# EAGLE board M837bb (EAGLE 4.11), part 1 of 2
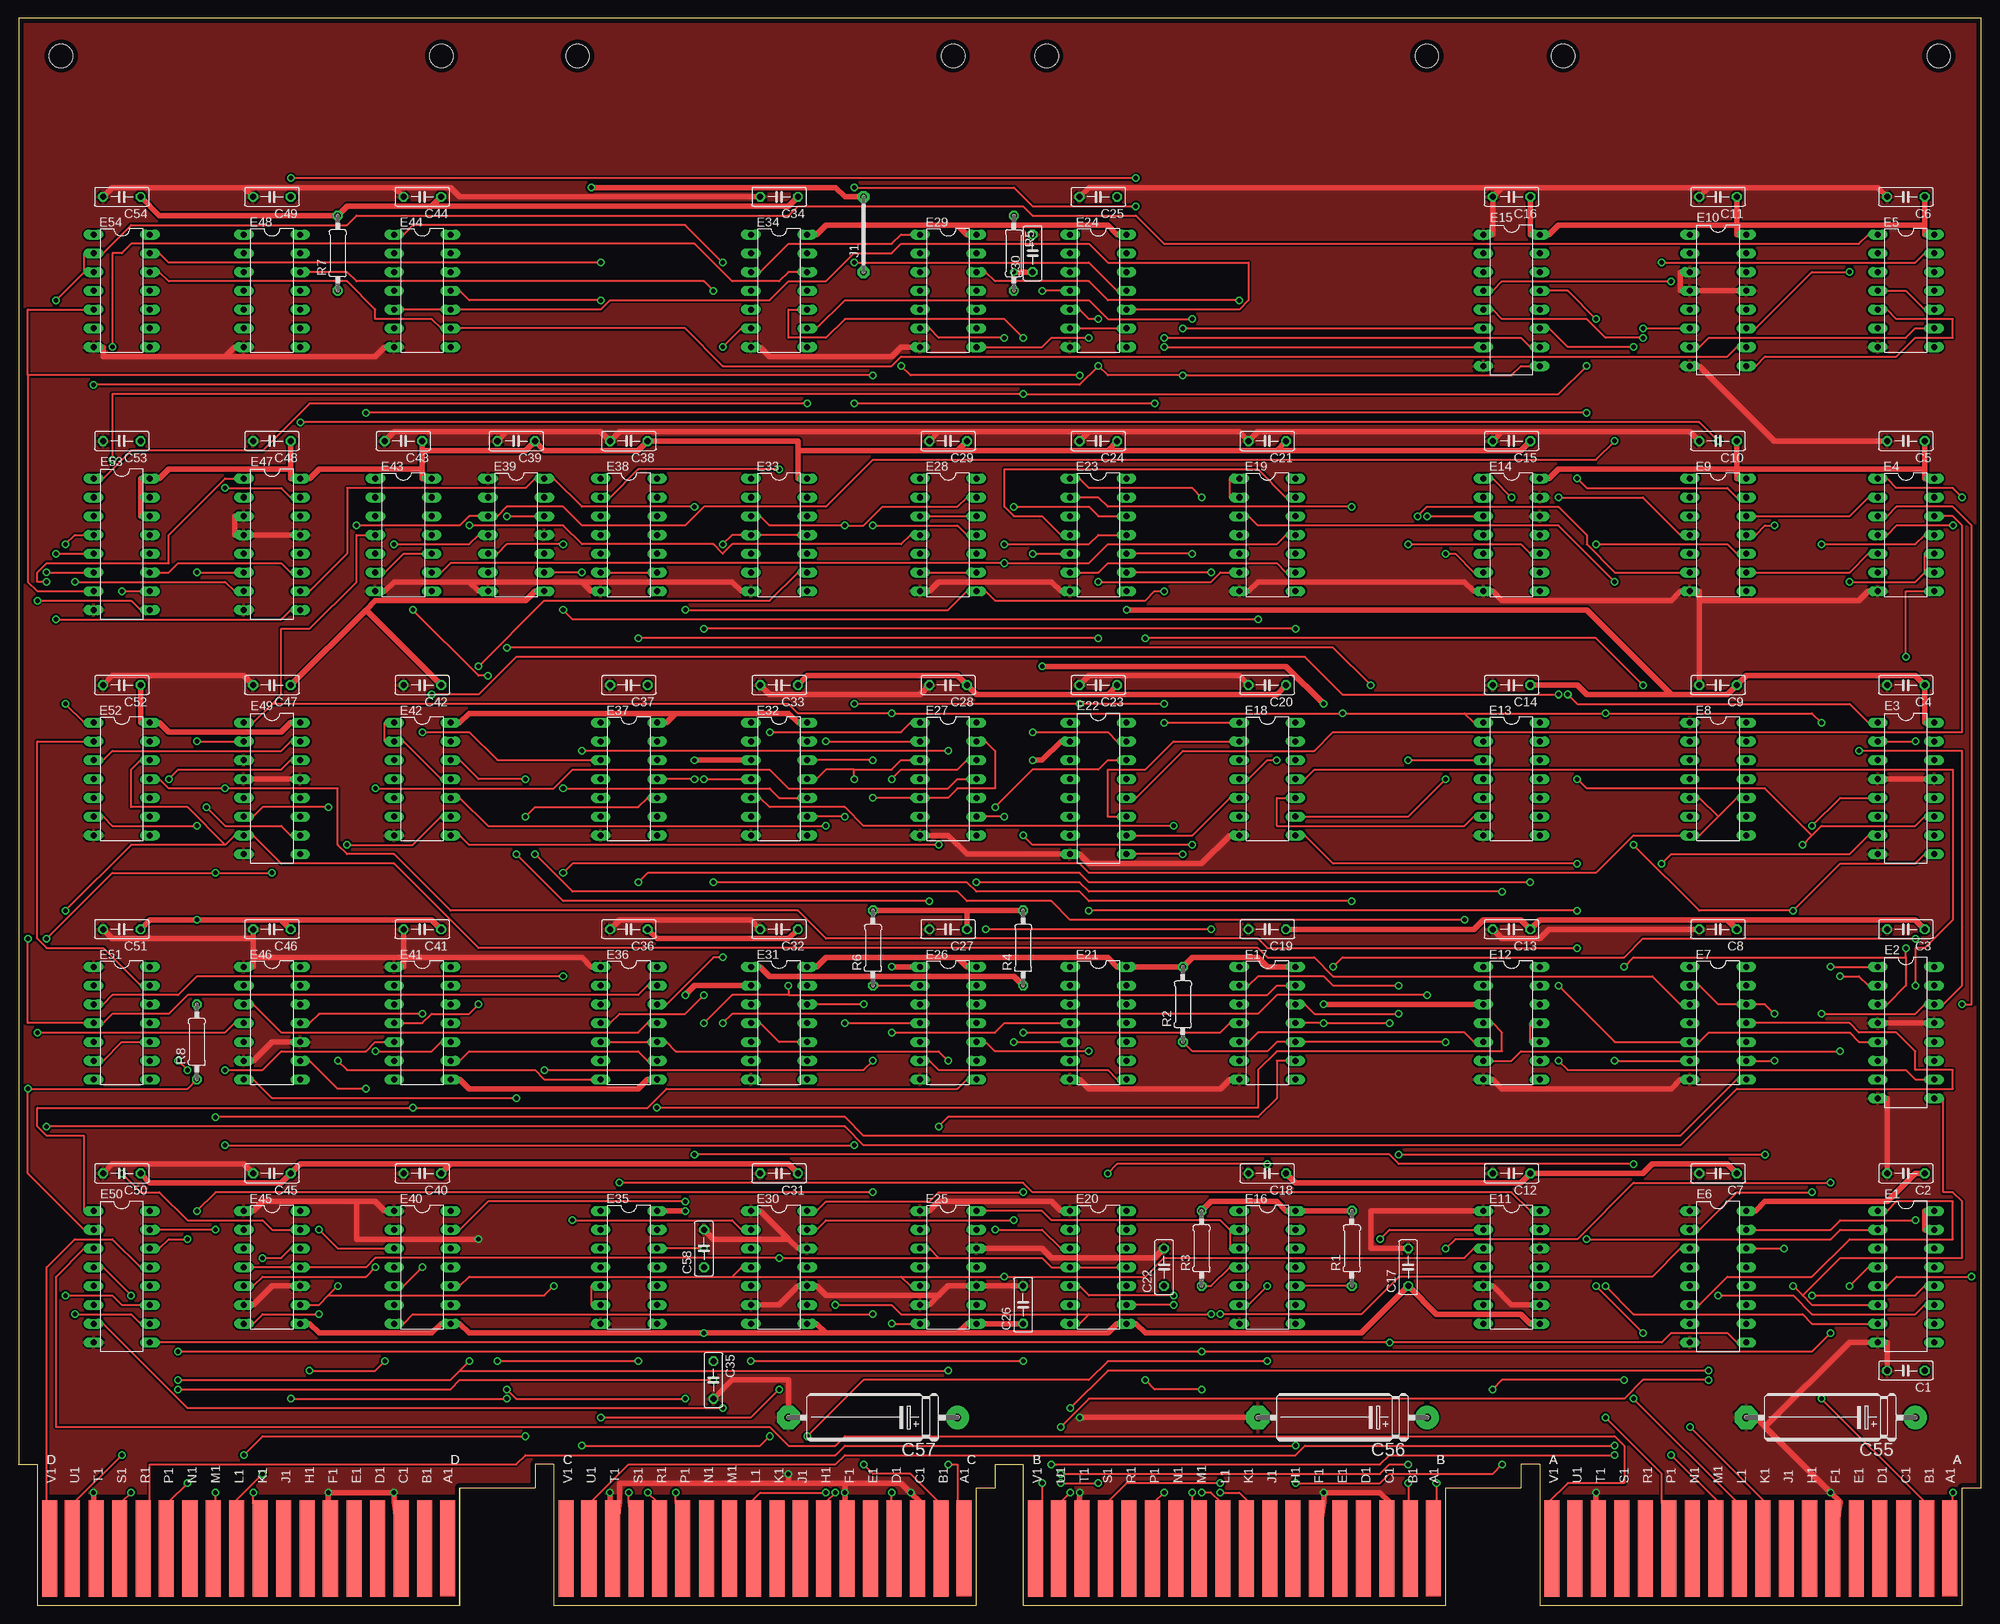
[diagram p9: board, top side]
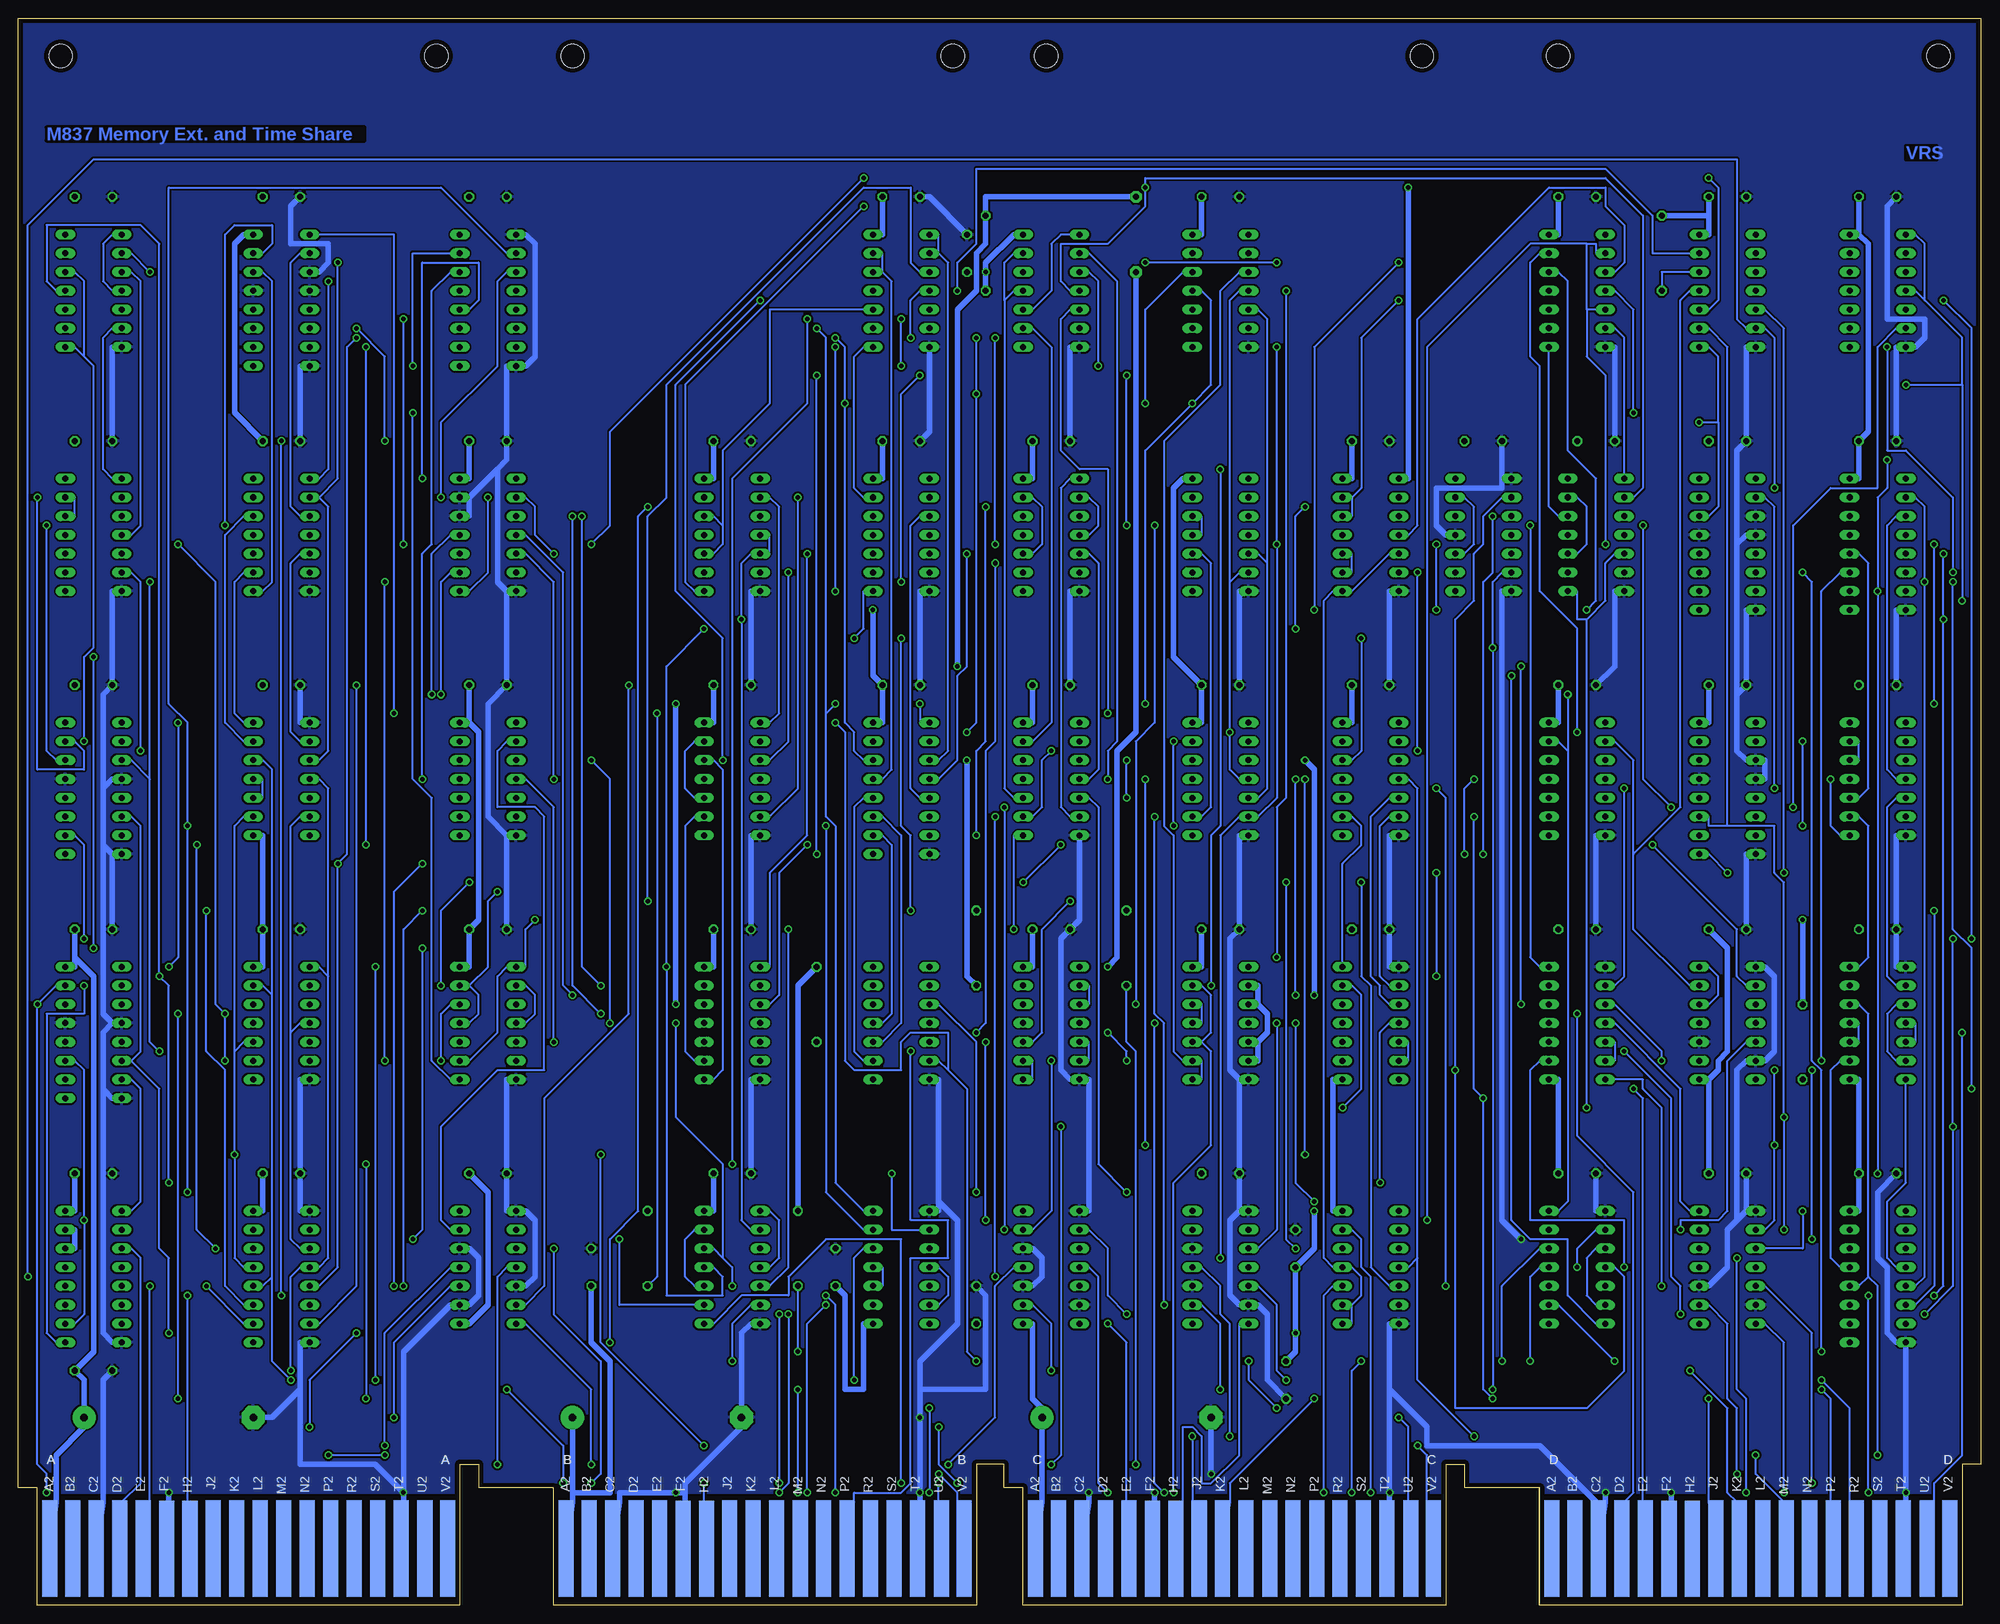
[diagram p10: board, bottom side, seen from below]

Size 265.43 x 214.63 mm. Coordinates in mm from the lower left corner, seen from the top.
Copper layers (1*16): Top 0.035mm / dielectric 1.5mm / Bottom 0.035mm
Design rules "default": minimum track width 10mil, minimum drill 24mil, track to track 8mil, track to pad 8mil, pad to pad 8mil, via to via 8mil, smd to smd 8mil, copper to edge 25mil, drill to drill 8mil, minimum pad ring 10mil, minimum via ring 8mil, stop-mask expansion 4mil, vias tented up to drill 0mil, thermal gap 10mil
Net classes: 1 Supply: width 0.762 mm

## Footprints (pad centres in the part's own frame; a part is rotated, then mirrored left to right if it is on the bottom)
C050-025X075 = drill 0.813 octagon: 1 -2.54,0; 2 2.54,0
E22-6 = drill 1.016 pad 3.15 round: + -11.43,0 | drill 1.016 pad 3.15 octagon: - 11.43,0
DIL16 = drill 0.813 long: 1 -8.89,-3.81; 2 -6.35,-3.81; 3 -3.81,-3.81; 4 -1.27,-3.81; 5 1.27,-3.81; 6 3.81,-3.81; 7 6.35,-3.81; 8 8.89,-3.81; 9 8.89,3.81; 10 6.35,3.81; 11 3.81,3.81; 12 1.27,3.81; 13 -1.27,3.81; 14 -3.81,3.81; 15 -6.35,3.81; 16 -8.89,3.81
DIL14 = drill 0.813 long: 1 -7.62,-3.81; 2 -5.08,-3.81; 3 -2.54,-3.81; 4 0,-3.81; 5 2.54,-3.81; 6 5.08,-3.81; 7 7.62,-3.81; 8 7.62,3.81; 9 5.08,3.81; 10 2.54,3.81; 11 0,3.81; 12 -2.54,3.81; 13 -5.08,3.81; 14 -7.62,3.81
EDGE-CON8 = smd 2.032 x 13.017: AA1 261.223,7.709; AB1 258.118,7.684; AC1 254.956,7.684; AD1 251.765,7.684; AE1 248.59,7.693; AF1 245.389,7.668; AH1 242.24,7.668; AJ1 239.09,7.668; AK1 235.915,7.668; AL1 232.74,7.693; AM1 229.54,7.693; AN1 226.39,7.693; AP1 223.19,7.668; AR1 220.04,7.668; AS1 216.865,7.693; AT1 213.69,7.693; AU1 210.49,7.693; AV1 207.404,7.668; BA1 191.373,7.709; BB1 188.268,7.684; BC1 185.106,7.684; BD1 181.915,7.684; BE1 178.74,7.693; BF1 175.539,7.668; BH1 172.39,7.668; BJ1 169.24,7.668; BK1 166.065,7.668; BL1 162.89,7.693; BM1 159.69,7.693; BN1 156.54,7.693; BP1 153.34,7.668; BR1 150.19,7.668; BS1 147.015,7.693; BT1 143.84,7.693; BU1 140.64,7.693; BV1 137.554,7.668; CA1 127.873,7.709; CB1 124.768,7.684; CC1 121.606,7.684; CD1 118.415,7.684; CE1 115.24,7.693; CF1 112.039,7.668; CH1 108.89,7.668; CJ1 105.74,7.668; CK1 102.565,7.668; CL1 99.39,7.693; CM1 96.19,7.693; CN1 93.04,7.693; CP1 89.84,7.668; CR1 86.69,7.668; CS1 83.515,7.693; CT1 80.34,7.693; CU1 77.14,7.693; CV1 74.054,7.668; DA1 58.023,7.709; DB1 54.918,7.684; DC1 51.756,7.684; DD1 48.565,7.684; DE1 45.39,7.693; DF1 42.189,7.668; DH1 39.04,7.668; DJ1 35.89,7.668; DK1 32.715,7.668; DL1 29.54,7.693; DM1 26.34,7.693; DN1 23.19,7.693; DP1 19.99,7.668; DR1 16.84,7.668; DS1 13.665,7.693; DT1 10.49,7.693; DU1 7.29,7.693; DV1 4.204,7.668 | smd 2.032 x 13.017 bottom: AA2 261.223,7.69; AB2 258.102,7.668; AC2 254.94,7.668; AD2 251.765,7.693; AE2 248.59,7.693; AF2 245.389,7.642; AH2 242.24,7.642; AJ2 239.09,7.668; AK2 235.915,7.668; AL2 232.74,7.693; AM2 229.54,7.693; AN2 226.39,7.693; AP2 223.19,7.668; AR2 220.04,7.668; AS2 216.865,7.693; AT2 213.69,7.693; AU2 210.464,7.693; AV2 207.404,7.668; BA2 191.373,7.69; BB2 188.252,7.668; BC2 185.09,7.668; BD2 181.915,7.693; BE2 178.74,7.693; BF2 175.539,7.642; BH2 172.39,7.642; BJ2 169.24,7.668; BK2 166.065,7.668; BL2 162.89,7.693; BM2 159.69,7.693; BN2 156.54,7.693; BP2 153.34,7.668; BR2 150.19,7.668; BS2 147.015,7.693; BT2 143.84,7.693; BU2 140.614,7.693; BV2 137.554,7.668; CA2 127.873,7.69; CB2 124.752,7.668; CC2 121.59,7.668; CD2 118.415,7.693; CE2 115.24,7.693; CF2 112.039,7.642; CH2 108.89,7.642; CJ2 105.74,7.668; CK2 102.565,7.668; CL2 99.39,7.693; CM2 96.19,7.693; CN2 93.04,7.693; CP2 89.84,7.668; CR2 86.69,7.668; CS2 83.515,7.693; CT2 80.34,7.693; CU2 77.114,7.693; CV2 74.054,7.668; DA2 58.023,7.69; DB2 54.902,7.668; DC2 51.74,7.668; DD2 48.565,7.693; DE2 45.39,7.693; DF2 42.189,7.642; DH2 39.04,7.642; DJ2 35.89,7.668; DK2 32.715,7.668; DL2 29.54,7.693; DM2 26.34,7.693; DN2 23.19,7.693; DP2 19.99,7.668; DR2 16.84,7.668; DS2 13.665,7.693; DT2 10.49,7.693; DU2 7.264,7.693; DV2 4.204,7.668
10 = drill 0.813 pad 1.6 octagon: 1 -5.08,0; 2 5.08,0
0207/10 = drill 0.813 octagon: 1 -5.08,0; 2 5.08,0
OMNIBUS = hole 3.175: 208.915,209.55; 259.715,209.55; 190.5,209.55; 139.065,209.55; 75.616,209.55; 126.416,209.55; 57.201,209.55; 5.766,209.55

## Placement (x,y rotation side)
C1  .01uf  [C050-025X075]  255.27,31.75 180 top
C2  .01uf  [C050-025X075]  255.27,58.42 180 top
C3  .01uf  [C050-025X075]  255.27,91.44 180 top
C4  .01uf  [C050-025X075]  255.27,124.46 180 top
C5  .01uf  [C050-025X075]  255.27,157.48 180 top
C6  .01uf  [C050-025X075]  255.27,190.5 180 top
C7  .01uf  [C050-025X075]  229.87,58.42 180 top
C8  .01uf  [C050-025X075]  229.87,91.44 180 top
C9  .01uf  [C050-025X075]  229.87,124.46 180 top
C10  .01uf  [C050-025X075]  229.87,157.48 180 top
C11  .01uf  [C050-025X075]  229.87,190.5 180 top
C12  .01uf  [C050-025X075]  201.93,58.42 180 top
C13  .01uf  [C050-025X075]  201.93,91.44 180 top
C14  .01uf  [C050-025X075]  201.93,124.46 180 top
C15  .01uf  [C050-025X075]  201.93,157.48 180 top
C16  .01uf  [C050-025X075]  201.93,190.5 180 top
C17  .01uf  [C050-025X075]  187.96,45.72 90 top
C18  .01uf  [C050-025X075]  168.91,58.42 180 top
C19  .01uf  [C050-025X075]  168.91,91.44 180 top
C20  .01uf  [C050-025X075]  168.91,124.46 180 top
C21  .01uf  [C050-025X075]  168.91,157.48 180 top
C22  .01uf  [C050-025X075]  154.94,45.72 90 top
C23  .01uf  [C050-025X075]  146.05,124.46 180 top
C24  .01uf  [C050-025X075]  146.05,157.48 180 top
C25  .01uf  [C050-025X075]  146.05,190.5 180 top
C26  .01uf  [C050-025X075]  135.89,40.64 90 top
C27  .01uf  [C050-025X075]  125.73,91.44 180 top
C28  .01uf  [C050-025X075]  125.73,124.46 180 top
C29  .01uf  [C050-025X075]  125.73,157.48 180 top
C30  .01uf  [C050-025X075]  137.16,182.88 90 top
C31  .01uf  [C050-025X075]  102.87,58.42 180 top
C32  .01uf  [C050-025X075]  102.87,91.44 180 top
C33  .01uf  [C050-025X075]  102.87,124.46 180 top
C34  .01uf  [C050-025X075]  102.87,190.5 180 top
C35  .01uf  [C050-025X075]  93.98,30.48 270 top
C36  .01uf  [C050-025X075]  82.55,91.44 180 top
C37  .01uf  [C050-025X075]  82.55,124.46 180 top
C38  .01uf  [C050-025X075]  82.55,157.48 180 top
C39  .01uf  [C050-025X075]  67.31,157.48 180 top
C40  .01uf  [C050-025X075]  54.61,58.42 180 top
C41  .01uf  [C050-025X075]  54.61,91.44 180 top
C42  .01uf  [C050-025X075]  54.61,124.46 180 top
C43  .01uf  [C050-025X075]  52.07,157.48 180 top
C44  .01uf  [C050-025X075]  54.61,190.5 180 top
C45  .01uf  [C050-025X075]  34.29,58.42 180 top
C46  .01uf  [C050-025X075]  34.29,91.44 180 top
C47  .01uf  [C050-025X075]  34.29,124.46 180 top
C48  .01uf  [C050-025X075]  34.29,157.48 180 top
C49  .01uf  [C050-025X075]  34.29,190.5 180 top
C50  .01uf  [C050-025X075]  13.97,58.42 180 top
C51  .01uf  [C050-025X075]  13.97,91.44 180 top
C52  .01uf  [C050-025X075]  13.97,124.46 180 top
C53  .01uf  [C050-025X075]  13.97,157.48 180 top
C54  .01uf  [C050-025X075]  13.97,190.5 180 top
C55  6.8uf  [E22-6]  245.11,25.4 180 top
C56  6.8uf  [E22-6]  179.07,25.4 180 top
C57  6.8uf  [E22-6]  115.57,25.4 180 top
C58  .01uf  [C050-025X075]  92.71,48.26 90 top
E1  DEC8235  [DIL16]  255.27,44.45 270 top
E2  DEC8271  [DIL16]  255.27,77.47 270 top
E3  DEC8271  [DIL16]  255.27,110.49 270 top
E4  7400N  [DIL14]  255.27,144.78 270 top
E5  7400N  [DIL14]  255.27,177.8 270 top
E6  DEC8235  [DIL16]  229.87,44.45 270 top
E7  DS8881N  [DIL14]  229.87,78.74 270 top
E8  SP384N  [DIL14]  229.87,111.76 270 top
E9  7400N  [DIL14]  229.87,144.78 270 top
E10  DEC8271  [DIL16]  229.87,176.53 270 top
E11  SP380N  [DIL14]  201.93,45.72 270 top
E12  7410N  [DIL14]  201.93,78.74 270 top
E13  74S74N  [DIL14]  201.93,111.76 270 top
E14  7400N  [DIL14]  201.93,144.78 270 top
E15  8266  [DIL16]  201.93,176.53 270 top
E16  DS8881N  [DIL14]  168.91,45.72 270 top
E17  74S74N  [DIL14]  168.91,78.74 270 top
E18  74H00N  [DIL14]  168.91,111.76 270 top
E19  7400N  [DIL14]  168.91,144.78 270 top
E20  SP380N  [DIL14]  146.05,45.72 270 top
E21  7410N  [DIL14]  146.05,78.74 270 top
E22  DEC8251  [DIL16]  146.05,110.49 270 top
E23  7404N  [DIL14]  146.05,144.78 270 top
E24  7400N  [DIL14]  146.05,177.8 270 top
E25  SP384N  [DIL14]  125.73,45.72 270 top
E26  DS8881N  [DIL14]  125.73,78.74 270 top
E27  7404N  [DIL14]  125.73,111.76 270 top
E28  7400N  [DIL14]  125.73,144.78 270 top
E29  7410N  [DIL14]  125.73,177.8 270 top
E30  SP384N  [DIL14]  102.87,45.72 270 top
E31  DS8881N  [DIL14]  102.87,78.74 270 top
E32  SP314N  [DIL14]  102.87,111.76 270 top
E33  SP314N  [DIL14]  102.87,144.78 270 top
E34  SP314N  [DIL14]  102.87,177.8 270 top
E35  DS8881N  [DIL14]  82.55,45.72 270 top
E36  SP380N  [DIL14]  82.55,78.74 270 top
E37  SP314N  [DIL14]  82.55,111.76 270 top
E38  7420  [DIL14]  82.55,144.78 270 top
E39  SP380N  [DIL14]  67.31,144.78 270 top
E40  SP380N  [DIL14]  54.61,45.72 270 top
E41  SP384N  [DIL14]  54.61,78.74 270 top
E42  7410N  [DIL14]  54.61,111.76 270 top
E43  7420  [DIL14]  52.07,144.78 270 top
E44  7400N  [DIL14]  54.61,177.8 270 top
E45  SP380N  [DIL14]  34.29,45.72 270 top
E46  SP380N  [DIL14]  34.29,78.74 270 top
E47  DEC8271  [DIL16]  34.29,143.51 270 top
E48  7404N  [DIL14]  34.29,177.8 270 top
E49  DEC8271  [DIL16]  34.29,110.49 270 top
E50  DEC8235  [DIL16]  13.97,44.45 270 top
E51  SP384N  [DIL14]  13.97,78.74 270 top
E52  7400N  [DIL14]  13.97,111.76 270 top
E53  8266  [DIL16]  13.97,143.51 270 top
E54  7410N  [DIL14]  13.97,177.8 270 top
EDGE  [EDGE-CON8]  0,0 0 top
J1  J10MM  [10]  114.3,185.42 90 top
R1  1K  [0207/10]  180.34,48.26 90 top
R2  1K  [0207/10]  157.48,81.28 90 top
R3  1K  [0207/10]  160.02,48.26 90 top
R4  1K  [0207/10]  135.89,88.9 90 top
R5  1K  [0207/10]  134.62,182.88 270 top
R6  1K  [0207/10]  115.57,88.9 90 top
R7  1K  [0207/10]  43.18,182.88 90 top
R8  1K  [0207/10]  24.13,76.2 90 top
U$1  OUTLINE-OMNIBUS  [OMNIBUS]  0,0 0 top

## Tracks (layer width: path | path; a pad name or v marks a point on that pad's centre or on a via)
(D_IN+CIF+RMF)
  Top 0.254: E10.10 232.41,170.18 231.14,168.91 119.38,168.91 118.11,167.64 95.25,167.64 90.17,172.72 E44.9 57.15,172.72 55.88,173.99 48.26,173.99 48.26,175.26 44.45,179.07 20.32,179.07 19.05,180.34 E54.12
(DF_ENAB*EMA_DISAB\)\  (via drill 0.61)
  Top 0.254: v210.82,100.33 177.8,100.33 173.99,104.14 E18.8 | v214.63,43.18 218.44,39.37 241.3,39.37 242.57,38.1 E1.7
  Bottom 0.254: v210.82,100.33 214.63,96.52 v214.63,43.18
(DF_ENAB\*EMA_DISAB\)\  (via drill 0.61)
  Top 0.254: v256.54,83.82 256.54,88.9 257.81,88.9 261.62,92.71 261.62,113.03 175.26,113.03 173.99,111.76 E18.11
  Bottom 0.254: v256.54,83.82 256.54,80.01 261.62,80.01 261.62,36.83 260.35,35.56 E1.9
(GTF+RIB)\  (via drill 0.61)
  Top 0.254: E50.9 v185.42,35.56 222.25,35.56 223.52,36.83 231.14,36.83 232.41,35.56 E6.9 | v180.34,148.59 147.32,148.59 146.05,149.86 E23.2
  Bottom 0.254: v180.34,148.59 181.61,147.32 181.61,53.34 185.42,49.53 v185.42,35.56
(IND+RIF)\  (via drill 0.61)
  Top 0.254: v219.71,124.46 213.36,130.81 v152.4,130.81
  Bottom 0.254: v219.71,124.46 219.71,43.18 224.79,38.1 E6.7 | v152.4,130.81 151.13,132.08 151.13,137.16 E23.8
(LA+TP3)\  (via drill 0.61)
  Top 0.254: v41.91,107.95 33.02,107.95 31.75,106.68 E49.6 | v45.72,146.05 59.69,146.05 60.96,147.32 E39.3 64.77,147.32 66.04,148.59 73.66,148.59 76.2,146.05 90.17,146.05 92.71,148.59 109.22,148.59 115.57,154.94 213.36,154.94 v215.9,157.48 | v219.71,172.72 E10.6
  Bottom 0.254: v41.91,107.95 45.72,111.76 v45.72,146.05 | v219.71,172.72 215.9,168.91 v215.9,157.48
(LA+TP4*LD_CTL)\  (via drill 0.61)
  Top 0.254: v21.59,34.29 v160.02,34.29 242.57,34.29 v245.11,36.83 | v24.13,139.7 E47.6 | R3.1 161.29,43.18 163.83,45.72 E16.4
  Bottom 0.254: 250.19,73.66 248.92,74.93 248.92,105.41 250.19,106.68 E3.6 | v24.13,139.7 22.86,138.43 22.86,73.66 21.59,72.39 v21.59,34.29 | v160.02,34.29 R3.1 | E16.1 163.83,53.34 162.56,52.07 162.56,46.99 163.83,45.72 E16.4 | 250.19,73.66 246.38,69.85 246.38,48.26 245.11,46.99 v245.11,36.83 | 250.19,73.66 E2.6
[D_IN+D(JMP+JMS)+(F*MD3)\(JMP+JMS)]  (via drill 0.61)
  Top 0.254: v208.28,73.66 209.55,72.39 255.27,72.39 256.54,71.12 E2.10
  Bottom 0.254: v208.28,73.66 208.28,80.01 207.01,81.28 E12.12
BUF_D_IN\  (via drill 0.61)
  Top 0.254: E51.6 11.43,73.66 13.97,76.2 E51.10 | 229.87,106.68 232.41,109.22 E8.10 | 229.87,106.68 227.33,104.14 E8.7 218.44,104.14 213.36,99.06 144.78,99.06 143.51,100.33 74.93,100.33 v73.66,99.06 | 229.87,106.68 227.33,109.22 E8.5 | v73.66,85.09 24.13,85.09 21.59,82.55 12.7,82.55 11.43,81.28 E51.3
  Bottom 0.254: E51.3 11.43,81.28 12.7,80.01 12.7,74.93 11.43,73.66 E51.6 | E51.11 16.51,78.74 16.51,76.2 E51.10 | E8.11 232.41,111.76 232.41,109.22 E8.10 | v73.66,99.06 v73.66,85.09
C1L  (via drill 0.61)
  Top 0.254: v110.49,15.24 109.22,13.97 EDGE.CH1 | v111.76,78.74 E26.4
  Bottom 0.254: v111.76,78.74 111.76,16.51 v110.49,15.24
CDF\  (via drill 0.61)
  Top 0.254: 1.27,166.37 1.27,175.26 E54.5 | 1.27,166.37 1.27,138.43 2.54,137.16 E53.7 | v115.57,146.05 127,146.05 128.27,144.78 E28.11 | v115.57,166.37 1.27,166.37
  Bottom 0.254: v115.57,146.05 v115.57,166.37
CIF\  (via drill 0.61)
  Top 0.254: v154.94,137.16 153.67,137.16 152.4,135.89 132.08,135.89 130.81,137.16 E28.8 128.27,137.16 125.73,134.62 v90.17,134.62 | v154.94,170.18 E15.7 | v78.74,181.61 20.32,181.61 19.05,182.88 E54.13
  Bottom 0.254: v154.94,137.16 v154.94,170.18 | v78.74,181.61 90.17,170.18 v90.17,134.62
CINT  (via drill 0.61)
  Top 0.254: v113.03,181.61 144.78,181.61 148.59,177.8 E24.11 | v95.25,181.61 90.17,186.69 53.34,186.69 52.07,185.42 E44.1
  Bottom 0.254: v95.25,181.61 v113.03,181.61
CINT\
  Bottom 0.254: 148.59,180.34 147.32,179.07 147.32,113.03 148.59,111.76 E22.13 | 148.59,180.34 148.59,182.88 E24.13 | 148.59,180.34 E24.12
CPMA_DISABLE
  Bottom 0.254: E11.13 207.01,50.8 208.28,52.07 208.28,64.77 200.66,72.39 194.31,72.39 194.31,106.68 195.58,107.95 200.66,107.95 200.66,115.57 199.39,116.84 E13.2
CPMA_DISABLE\  (via drill 0.61)
  Top 0.254: v215.9,21.59 173.99,21.59 172.72,20.32 111.76,20.32 110.49,19.05 82.55,19.05 77.47,13.97 EDGE.CU1
  Bottom 0.254: v215.9,21.59 215.9,36.83 207.01,45.72 E11.11
CUF\  (via drill 0.61)
  Top 0.254: v137.16,142.24 E23.5
  Bottom 0.254: v137.16,142.24 137.16,127 138.43,125.73 138.43,114.3 140.97,111.76 E22.4
D  (via drill 0.61)
  Top 0.254: v208.28,123.19 179.07,123.19 173.99,128.27 67.31,128.27 62.23,123.19 v55.88,123.19
  Bottom 0.254: 55.88,115.57 55.88,54.61 57.15,53.34 E40.14 | 55.88,115.57 57.15,116.84 E42.13 | v208.28,123.19 208.28,138.43 207.01,139.7 E14.9 | v55.88,123.19 55.88,115.57
D\  (via drill 0.61)
  Top 0.254: v49.53,33.02 48.26,31.75 v39.37,31.75
  Bottom 0.254: v49.53,33.02 57.15,40.64 E40.9 | v39.37,31.75 34.29,26.67 34.29,15.24 33.02,13.97 EDGE.DK2
D_IN\  (via drill 0.61)
  Top 0.254: E5.10 257.81,175.26 255.27,177.8 E5.4 | 8.89,180.34 8.89,182.88 E54.2 11.43,182.88 15.24,186.69 44.45,186.69 45.72,187.96 104.14,187.96 105.41,189.23 135.89,189.23 137.16,187.96 151.13,187.96 154.94,184.15 248.92,184.15 250.19,185.42 E5.1 | E36.13 85.09,83.82 83.82,82.55 22.86,82.55 20.32,80.01 12.7,80.01 11.43,78.74 E51.4 1.27,78.74 v1.27,90.17 | v5.08,176.53 8.89,180.34 | 8.89,180.34 E54.3 | v86.36,67.31 167.64,67.31 167.64,72.39 170.18,74.93 200.66,74.93 200.66,77.47 199.39,78.74 E12.4
  Bottom 0.254: E5.1 252.73,185.42 254,184.15 254,179.07 252.73,177.8 E5.4 | E12.4 196.85,78.74 195.58,80.01 195.58,82.55 196.85,83.82 E12.2 | E51.5 8.89,76.2 8.89,78.74 E51.4 | v5.08,176.53 1.27,172.72 v1.27,90.17 | v86.36,67.31 83.82,69.85 83.82,82.55 85.09,83.82 E36.13
DATA03\
  Top 0.254: E50.3 8.89,48.26 5.08,44.45 5.08,24.13 101.6,24.13 104.14,21.59 110.49,21.59 111.76,22.86 215.9,22.86 217.17,21.59 217.17,16.51 209.55,16.51 207.01,13.97 EDGE.AV1
DATA05\  (via drill 0.61)
  Top 0.254: v162.56,16.51 149.86,16.51 147.32,13.97 EDGE.BS1 | v162.56,39.37 181.61,39.37 186.69,44.45 220.98,44.45 224.79,48.26 E6.3
  Bottom 0.254: 228.6,77.47 228.6,49.53 227.33,48.26 E6.3 | 228.6,77.47 227.33,78.74 E7.4 | 228.6,77.47 228.6,105.41 227.33,106.68 E8.6 | v162.56,39.37 v162.56,16.51
DATA06\  (via drill 0.61)
  Top 0.254: v142.24,15.24 140.97,13.97 EDGE.BU1 | v142.24,26.67 147.32,31.75 v228.6,31.75
  Bottom 0.254: 223.52,85.09 223.52,46.99 224.79,45.72 E6.4 227.33,45.72 228.6,44.45 v228.6,31.75 | 223.52,85.09 224.79,86.36 E7.1 | 223.52,85.09 223.52,110.49 224.79,111.76 E8.4 | v142.24,26.67 v142.24,15.24
DATA07\  (via drill 0.61)
  Top 0.254: v138.43,16.51 138.43,13.97 EDGE.BV1 | v140.97,24.13 144.78,27.94 217.17,27.94 219.71,30.48 v228.6,30.48
  Bottom 0.254: 231.14,44.45 232.41,43.18 E6.12 | 231.14,44.45 231.14,82.55 | 231.14,82.55 232.41,83.82 E7.13 | 231.14,82.55 231.14,113.03 232.41,114.3 E8.12 | v138.43,16.51 140.97,19.05 v140.97,24.13 | v228.6,30.48 231.14,33.02 231.14,44.45
DATA08\  (via drill 0.61)
  Top 0.254: v172.72,21.59 111.76,21.59 110.49,20.32 68.58,20.32 67.31,19.05 17.78,19.05 17.78,13.97 EDGE.DR1 | v186.69,60.96 v236.22,60.96
  Bottom 0.254: 236.22,74.93 v236.22,60.96 236.22,46.99 234.95,45.72 E6.13 | 236.22,74.93 234.95,76.2 E7.10 | 236.22,74.93 236.22,105.41 234.95,106.68 E8.9 | v172.72,21.59 186.69,35.56 v186.69,60.96
DATA09\  (via drill 0.61)
  Top 0.254: v15.24,41.91 11.43,45.72 E50.4 | v15.24,15.24 13.97,13.97 EDGE.DS1
  Bottom 0.254: E51.7 10.16,57.15 12.7,54.61 12.7,46.99 11.43,45.72 E50.4 | v15.24,15.24 v15.24,41.91
DATA10\  (via drill 0.61)
  Top 0.254: v13.97,20.32 7.62,13.97 EDGE.DU1
  Bottom 0.254: 15.24,44.45 16.51,43.18 E50.12 | 15.24,44.45 15.24,80.01 16.51,81.28 E51.12 | v13.97,20.32 13.97,43.18 15.24,44.45
DATA11\
  Top 0.254: E50.13 16.51,45.72 12.7,49.53 7.62,49.53 3.81,45.72 3.81,13.97 EDGE.DV1
  Bottom 0.254: E50.13 19.05,45.72 20.32,46.99 20.32,72.39 19.05,73.66 E51.9
DB
  Top 0.254: E17.5 166.37,76.2 167.64,77.47 195.58,77.47 196.85,76.2 E12.5
DB_LOAD  (via drill 0.61)
  Top 0.254: v186.69,83.82 177.8,83.82 176.53,85.09 167.64,85.09 166.37,83.82 E17.2 | v189.23,147.32 190.5,148.59 208.28,148.59 212.09,144.78 212.09,143.51 215.9,139.7 E9.6
  Bottom 0.254: v186.69,83.82 189.23,86.36 v189.23,147.32
EMA0\
  Bottom 0.254: E1.3 250.19,48.26 248.92,46.99 248.92,16.51 251.46,13.97 EDGE.AD2
EMA1\  (via drill 0.61)
  Top 0.254: v247.65,43.18 250.19,45.72 E1.4
  Bottom 0.254: v247.65,43.18 247.65,13.97 EDGE.AE2
EMA2\  (via drill 0.61)
  Top 0.254: v242.57,41.91 256.54,41.91 257.81,43.18 E1.12
  Bottom 0.254: v242.57,41.91 242.57,13.97 EDGE.AH2
ERROR  (via drill 0.61)
  Top 0.254: v54.61,118.11 60.96,118.11 64.77,114.3 E37.3
  Bottom 0.254: v54.61,118.11 54.61,132.08 59.69,137.16 59.69,167.64 60.96,168.91 60.96,181.61 59.69,182.88 E44.13
EXT_LD\  (via drill 0.61)
  Top 0.254: v40.64,50.8 43.18,48.26 E40.3
  Bottom 0.254: E40.6 52.07,40.64 53.34,41.91 53.34,46.99 52.07,48.26 E40.3 | v40.64,50.8 40.64,52.07 35.56,52.07 34.29,53.34 34.29,73.66 31.75,76.2 E46.5
F  (via drill 0.61)
  Top 0.254: v44.45,102.87 53.34,102.87 57.15,106.68 E42.9
  Bottom 0.254: v44.45,102.87 33.02,91.44 33.02,85.09 31.75,83.82 E46.2
F\  (via drill 0.61)
  Top 0.254: v67.31,68.58 34.29,68.58 31.75,71.12 E46.7 | v68.58,106.68 69.85,107.95 83.82,107.95 85.09,109.22 E37.10 | v36.83,27.94 v66.04,27.94
  Bottom 0.254: v68.58,106.68 68.58,69.85 v67.31,68.58 67.31,29.21 v66.04,27.94 | v36.83,27.94 36.83,13.97 EDGE.DJ2
F_SET\  (via drill 0.61)
  Top 0.254: v93.98,30.48 59.69,30.48 58.42,29.21 v21.59,29.21
  Bottom 0.254: v93.98,30.48 95.25,31.75 95.25,40.64 97.79,43.18 E30.5 | v21.59,29.21 20.32,27.94 20.32,13.97 EDGE.DP2
GND  (via drill 0.61)
  Top 0.762: EDGE.BF1 176.53,13.97 v176.53,15.24 184.15,15.24 185.42,13.97 EDGE.BC1 | E27.7 125.73,104.14 128.27,101.6 E22.8 143.51,101.6 144.78,100.33 160.02,100.33 163.83,104.14 E18.7 | v143.51,15.24 143.51,13.97 EDGE.BT2 | E17.7 163.83,71.12 162.56,69.85 144.78,69.85 143.51,71.12 E21.7 | E25.1 123.19,53.34 124.46,54.61 139.7,54.61 140.97,53.34 E20.1 | v143.51,25.4 C56.- | EDGE.CF1 111.76,13.97 v111.76,15.24 111.76,16.51 | 111.76,16.51 119.38,16.51 v120.65,15.24 121.92,13.97 EDGE.CC1 | 104.14,16.51 111.76,16.51 | 104.14,16.51 81.28,16.51 81.28,13.97 EDGE.CT2 80.01,13.97 v80.01,15.24 | EDGE.DF1 41.91,13.97 v41.91,15.24 v50.8,15.24 50.8,13.97 EDGE.DC1 | 104.14,49.53 100.33,53.34 E30.1 | 104.14,49.53 105.41,48.26 E30.12 | C58.2 93.98,49.53 104.14,49.53 | E30.6 102.87,40.64 105.41,43.18 E30.10 107.95,43.18 109.22,41.91 124.46,41.91 | C35.2 96.52,30.48 104.14,30.48 C57.- | 124.46,41.91 125.73,43.18 E25.10 C26.2 | 124.46,41.91 123.19,40.64 E25.6 | C22.2 153.67,46.99 139.7,46.99 138.43,48.26 E25.12 | C32.2 99.06,92.71 81.28,92.71 C36.2 | 31.75,90.17 C46.2 | 31.75,87.63 31.75,90.17 | 31.75,87.63 31.75,86.36 E46.1 | 52.07,87.63 C41.2 | 52.07,87.63 52.07,86.36 E41.1 | 31.75,87.63 52.07,87.63 | C51.2 12.7,90.17 31.75,90.17 | 52.07,87.63 76.2,87.63 77.47,86.36 E36.1 | v10.16,15.24 10.16,13.97 EDGE.DT2 | E46.6 31.75,73.66 34.29,76.2 E46.10 | E45.6 31.75,40.64 34.29,43.18 E45.10 | C50.2 12.7,59.69 30.48,59.69 C45.2 | 45.72,54.61 33.02,54.61 31.75,53.34 E45.1 | 45.72,54.61 48.26,54.61 49.53,53.34 E40.1 | v104.14,17.78 104.14,16.51 | E11.5 199.39,43.18 201.93,40.64 E11.9 | C17.2 182.88,48.26 182.88,53.34 E11.1
  Top 0.762: E7.7 224.79,71.12 223.52,69.85 200.66,69.85 199.39,71.12 E12.7 | v213.36,15.24 213.36,13.97 EDGE.AT2 | 236.22,24.13 v245.11,15.24 246.38,13.97 EDGE.AF1 | 236.22,24.13 234.95,25.4 C55.- | C1.2 252.73,35.56 E1.8 247.65,35.56 236.22,24.13 | E2.4 E2.13 | C2.2 252.73,68.58 E2.8 | 227.33,135.89 C9.2 | 227.33,135.89 227.33,137.16 E9.7 224.79,137.16 223.52,135.89 200.66,135.89 199.39,137.16 E14.7 196.85,137.16 195.58,138.43 167.64,138.43 166.37,137.16 E19.7 | E3.4 E3.13 | 227.33,135.89 248.92,135.89 250.19,137.16 E4.7 | C54.2 12.7,191.77 30.48,191.77 | 30.48,191.77 C49.2 | 50.8,191.77 C44.2 | 30.48,191.77 50.8,191.77 | C34.2 59.69,190.5 58.42,191.77 50.8,191.77 | 66.04,158.75 78.74,158.75 C38.2 81.28,158.75 124.46,158.75 | 66.04,158.75 C39.2 | C43.2 50.8,158.75 66.04,158.75 | 27.94,168.91 11.43,168.91 11.43,170.18 E54.7 | 27.94,168.91 29.21,170.18 E48.7 | E47.3 29.21,147.32 29.21,144.78 E47.4 E47.13 | E49.4 E49.13 | C52.2 12.7,125.73 30.48,125.73 C47.2 | 27.94,168.91 48.26,168.91 49.53,170.18 E44.7 | E28.7 123.19,137.16 124.46,138.43 139.7,138.43 140.97,137.16 E23.7 | C20.2 165.1,125.73 144.78,125.73 C23.2 | 60.96,138.43 50.8,138.43 49.53,137.16 E43.7 | 60.96,138.43 62.23,137.16 E39.7 | 76.2,138.43 77.47,137.16 E38.7 | 76.2,138.43 60.96,138.43 | 76.2,138.43 96.52,138.43 97.79,137.16 E33.7 | C28.2 121.92,123.19 101.6,123.19 C33.2 | E10.3 224.79,180.34 224.79,177.8 E10.4 E10.13 | E15.1 199.39,185.42 C16.2 200.66,191.77 | 228.6,191.77 C11.2 | 228.6,191.77 251.46,191.77 C6.2 | 200.66,191.77 228.6,191.77 | C25.2 144.78,191.77 200.66,191.77 | E34.7 100.33,170.18 101.6,168.91 118.11,168.91 119.38,170.18 E29.7
  Top 0.762: 144.78,158.75 165.1,158.75 C21.2 167.64,158.75 200.66,158.75 | 144.78,158.75 C24.2 | 124.46,158.75 C29.2 | 144.78,158.75 124.46,158.75 | C8.2 207.01,91.44 205.74,90.17 200.66,90.17 C13.2 | C5.2 237.49,157.48 227.33,167.64 E10.8 | C10.2 226.06,158.75 200.66,158.75 | C15.2 200.66,158.75 | 45.72,54.61 45.72,49.53 v62.23,49.53
  Bottom 0.762: E16.7 166.37,38.1 167.64,36.83 C56.- 167.64,24.13 175.26,16.51 175.26,15.24 | 175.26,15.24 175.26,13.97 EDGE.BF2 | 175.26,15.24 v176.53,15.24 184.15,15.24 184.15,13.97 EDGE.BC2 | C19.2 166.37,104.14 E18.7 | E27.7 121.92,92.71 C27.2 124.46,90.17 124.46,72.39 123.19,71.12 E26.7 120.65,71.12 120.65,53.34 E25.1 | EDGE.BT2 143.51,13.97 v143.51,15.24 v143.51,25.4 143.51,29.21 | C18.2 166.37,71.12 E17.7 | 140.97,54.61 140.97,71.12 E21.7 | 140.97,54.61 140.97,53.34 E20.1 | 143.51,29.21 143.51,33.02 138.43,38.1 138.43,52.07 140.97,54.61 | v111.76,15.24 111.76,13.97 EDGE.CF2 | v120.65,15.24 120.65,13.97 EDGE.CC2 | v41.91,15.24 41.91,13.97 EDGE.DF2 | 80.01,29.21 v80.01,15.24 80.01,13.97 EDGE.CT2 | 80.01,29.21 80.01,38.1 E35.7 | 80.01,29.21 74.93,24.13 74.93,21.59 59.69,21.59 52.07,13.97 EDGE.DC2 50.8,13.97 v50.8,15.24 | 100.33,53.34 C31.2 100.33,71.12 | C35.2 96.52,30.48 96.52,39.37 97.79,40.64 E30.6 100.33,40.64 101.6,41.91 101.6,52.07 100.33,53.34 | E25.12 128.27,48.26 127,46.99 127,44.45 128.27,43.18 E25.10 | 100.33,53.34 E30.1 | E32.7 100.33,104.14 C32.2 101.6,90.17 101.6,72.39 100.33,71.12 | E36.1 80.01,86.36 C36.2 80.01,104.14 E37.7 | E51.1 11.43,86.36 C51.2 11.43,104.14 E52.7 | C46.2 31.75,101.6 E49.8 | C41.2 52.07,104.14 E42.7 | EDGE.DT2 10.16,13.97 v10.16,15.24 E50.8 11.43,35.56 12.7,36.83 12.7,45.72 13.97,46.99 13.97,55.88 C50.2 | C40.2 52.07,53.34 E40.1 | 31.75,53.34 C45.2 | 31.75,53.34 33.02,52.07 | 33.02,52.07 34.29,50.8 34.29,45.72 36.83,43.18 E45.10 | E45.1 31.75,53.34 | 33.02,52.07 33.02,72.39 31.75,73.66 E46.6 29.21,73.66 27.94,74.93 27.94,85.09 29.21,86.36 E46.1
  Bottom 0.762: 100.33,71.12 E31.7 | C57.- v104.14,17.78 | 143.51,29.21 134.62,29.21 134.62,41.91 C26.2 | E6.1 227.33,53.34 C7.2 227.33,71.12 E7.7 | E11.12 204.47,48.26 203.2,46.99 203.2,41.91 204.47,40.64 E11.9 207.01,40.64 213.36,34.29 v213.36,15.24 | E12.7 199.39,71.12 C12.2 199.39,53.34 E11.1 196.85,53.34 195.58,52.07 195.58,44.45 196.85,43.18 E11.5 | v213.36,15.24 213.36,13.97 EDGE.AT2 | 227.33,29.21 227.33,35.56 E6.8 | 227.33,29.21 231.14,25.4 C55.- | v213.36,15.24 217.17,19.05 227.33,19.05 227.33,29.21 | v245.11,15.24 245.11,13.97 EDGE.AF2 | C1.2 254,30.48 254,13.97 EDGE.AC2 | 252.73,78.74 254,77.47 254,69.85 | 254,69.85 252.73,68.58 E2.8 | C9.2 227.33,119.38 E8.1 | E4.7 252.73,137.16 C4.2 254,123.19 254,110.49 | 252.73,101.6 C3.2 | 254,110.49 252.73,111.76 E3.4 | 254,102.87 254,110.49 | 254,102.87 252.73,101.6 | 252.73,101.6 E3.8 | 252.73,78.74 254,80.01 254,102.87 | 252.73,78.74 E2.4 | 254,69.85 254,36.83 252.73,35.56 E1.8 | C43.2 49.53,170.18 E44.7 | C39.2 64.77,152.4 | 64.77,152.4 64.77,151.13 73.66,151.13 73.66,146.05 72.39,144.78 E39.11 | 64.77,152.4 E39.1 | C53.2 11.43,170.18 E54.7 8.89,170.18 7.62,171.45 7.62,173.99 12.7,173.99 12.7,189.23 C54.2 | E48.7 31.75,170.18 C48.2 33.02,156.21 33.02,143.51 | C52.2 11.43,134.62 E53.8 | E49.4 29.21,111.76 29.21,114.3 E49.3 31.75,114.3 33.02,115.57 33.02,123.19 | E47.8 31.75,134.62 C47.2 33.02,123.19 | 33.02,143.51 31.75,144.78 E47.4 | 33.02,143.51 33.02,123.19 | C20.2 166.37,137.16 E19.7 | C28.2 123.19,137.16 E28.7 | C23.2 143.51,137.16 E23.7 | C33.2 100.33,137.16 E33.7 | C37.2 80.01,137.16 E38.7 | C42.2 49.53,127 49.53,137.16 E43.7 | C30.2 142.24,190.5 C25.2
  Bottom 0.762: C11.2 228.6,189.23 228.6,184.15 223.52,184.15 223.52,181.61 224.79,180.34 E10.3 | C29.2 123.19,170.18 E29.7 | C24.2 142.24,158.75 E24.7 | 199.39,104.14 C13.2 | C10.2 227.33,167.64 E10.8 | C5.2 252.73,170.18 E5.7 | 199.39,137.16 C14.2 201.93,121.92 201.93,106.68 199.39,104.14 | 204.47,149.86 204.47,147.32 E14.12 | 200.66,153.67 199.39,154.94 C15.2 199.39,167.64 E15.8 196.85,167.64 195.58,168.91 195.58,184.15 196.85,185.42 E15.1 | 200.66,153.67 204.47,149.86 | 204.47,149.86 E14.13 | 199.39,137.16 200.66,138.43 200.66,153.67 | E14.7 199.39,137.16 | 199.39,104.14 E13.7 | v62.23,49.53 64.77,52.07 64.77,137.16 E39.7
  pour Bottom (isolate 0.254): 265.43,15.24 265.43,214.63 0,214.63 0,15.24
  pour Top (isolate 0.254): 265.43,15.24 265.43,214.63 0,214.63 0,15.24
GTF\  (via drill 0.61)
  Top 0.254: v170.18,114.3 168.91,114.3 166.37,111.76 E18.4 | v165.1,176.53 147.32,176.53 144.78,179.07 132.08,179.07 130.81,180.34 E29.12
  Bottom 0.254: v170.18,114.3 170.18,130.81 176.53,137.16 176.53,165.1 v165.1,176.53
IBIFDF_CLR\  (via drill 0.61)
  Top 0.254: R1.1 E16.10 | 34.29,121.92 35.56,123.19 35.56,132.08 39.37,132.08 45.72,138.43 45.72,144.78 E43.4 | 34.29,121.92 31.75,119.38 E49.1 | 195.58,120.65 196.85,119.38 E13.1 | 195.58,120.65 v179.07,120.65 v118.11,120.65 105.41,120.65 104.14,121.92 34.29,121.92 | v243.84,119.38 242.57,120.65 v214.63,120.65 195.58,120.65 | v245.11,86.36 E2.1
  Bottom 0.254: E16.13 173.99,50.8 175.26,49.53 175.26,44.45 173.99,43.18 E16.10 | v118.11,120.65 118.11,153.67 121.92,153.67 124.46,156.21 124.46,173.99 123.19,175.26 E29.5 | v245.11,86.36 243.84,87.63 v243.84,119.38 | v214.63,120.65 214.63,185.42 E10.1 | R1.1 179.07,44.45 v179.07,120.65
IND1\  (via drill 0.61)
  Top 0.254: v102.87,29.21 99.06,25.4 v78.74,25.4
  Bottom 0.254: v102.87,29.21 102.87,38.1 105.41,40.64 E30.9 | v78.74,25.4 77.47,24.13 77.47,13.97 EDGE.CU2
IND2\  (via drill 0.61)
  Top 0.254: v101.6,22.86 100.33,21.59 v76.2,21.59
  Bottom 0.254: v101.6,22.86 101.6,38.1 102.87,39.37 102.87,43.18 105.41,45.72 E30.11 | v76.2,21.59 74.93,20.32 74.93,13.97 EDGE.CV2
IND\  (via drill 0.61)
  Top 0.254: E19.1 163.83,152.4 163.83,149.86 E19.2 | v95.25,26.67 22.86,26.67 11.43,38.1 E50.7 | v135.89,33.02 v99.06,33.02 | v154.94,119.38 E18.1
  Bottom 0.254: E18.1 163.83,119.38 162.56,120.65 162.56,148.59 163.83,149.86 E19.2 | v95.25,26.67 99.06,30.48 v99.06,33.02 | v135.89,33.02 137.16,34.29 137.16,69.85 139.7,72.39 | 139.7,72.39 140.97,73.66 E21.6 | v154.94,119.38 153.67,118.11 153.67,73.66 152.4,72.39 146.05,72.39 146.05,76.2 144.78,77.47 139.7,77.47 139.7,72.39
INDH  (via drill 0.61)
  Top 0.254: v215.9,138.43 208.28,146.05 167.64,146.05 166.37,147.32 E19.3 | v215.9,73.66 E7.6
  Bottom 0.254: v215.9,73.66 v215.9,138.43
INITIALIZE  (via drill 0.61)
  Top 0.254: v83.82,33.02 v64.77,33.02 | v85.09,15.24 86.36,13.97 EDGE.CR1
  Bottom 0.254: v64.77,33.02 64.77,43.18 59.69,48.26 E40.12 | v83.82,33.02 85.09,31.75 v85.09,15.24
INITIALIZE\  (via drill 0.61)
  Top 0.254: v90.17,54.61 63.5,54.61 59.69,50.8 E40.13 | v92.71,78.74 96.52,82.55 104.14,82.55 | 104.14,82.55 168.91,82.55 170.18,83.82 E17.13 | v102.87,153.67 83.82,153.67 80.01,149.86 E38.2 | v104.14,83.82 104.14,82.55
  Bottom 0.254: v90.17,54.61 92.71,57.15 v92.71,78.74 | v102.87,153.67 102.87,105.41 104.14,104.14 v104.14,83.82
INT_IN_PROG_MAMS_LD_CTL  (via drill 0.61)
  Top 0.254: E47.10 39.37,137.16 44.45,142.24 44.45,151.13 68.58,151.13 69.85,152.4 E39.14 72.39,152.4 76.2,148.59 v91.44,148.59 | v177.8,86.36 179.07,87.63 217.17,87.63 219.71,90.17 v256.54,90.17 | v172.72,132.08 v92.71,132.08
  Bottom 0.254: v256.54,90.17 256.54,102.87 257.81,104.14 E3.10 | E16.11 171.45,45.72 170.18,44.45 170.18,41.91 177.8,41.91 v177.8,86.36 177.8,127 v172.72,132.08 | v91.44,148.59 92.71,147.32 v92.71,132.08
INT_IN_PROGRESS\  (via drill 0.61)
  Top 0.254: v144.78,74.93 132.08,74.93 130.81,76.2 E26.10 | v67.31,101.6 73.66,95.25 v123.19,95.25 | v66.04,147.32 E39.12
  Bottom 0.254: v144.78,74.93 144.78,52.07 139.7,52.07 139.7,46.99 144.78,46.99 144.78,16.51 146.05,15.24 152.4,15.24 152.4,13.97 EDGE.BP2 | v66.04,147.32 66.04,139.7 67.31,138.43 v67.31,101.6 | v123.19,95.25 127,91.44 127,77.47 128.27,76.2 E26.10
INT_INH  (via drill 0.61)
  Top 0.254: E50.1 8.89,53.34 8.89,63.5 3.81,63.5 2.54,64.77 2.54,67.31 v53.34,67.31 85.09,67.31 87.63,69.85 127,69.85 128.27,71.12 E26.8
  Bottom 0.254: 53.34,133.35 50.8,135.89 50.8,140.97 49.53,142.24 E43.5 | 53.34,133.35 54.61,133.35 54.61,137.16 E43.8 | E26.9 128.27,73.66 128.27,71.12 E26.8 | v53.34,67.31 53.34,133.35
INT_RQST\  (via drill 0.61)
  Top 0.254: v88.9,15.24 88.9,13.97 EDGE.CP1
  Bottom 0.254: v88.9,15.24 88.9,41.91 87.63,43.18 E35.10
INTERNAL_IO\  (via drill 0.61)
  Top 0.254: E31.4 100.33,78.74 102.87,76.2 E31.10 | v109.22,15.24 100.33,15.24 99.06,13.97 EDGE.CL1
  Bottom 0.254: 105.41,76.2 104.14,77.47 104.14,82.55 105.41,83.82 E31.13 | 105.41,76.2 104.14,74.93 104.14,62.23 109.22,57.15 v109.22,15.24 | 105.41,76.2 E31.10
IO_PAUSE\  (via drill 0.61)
  Top 0.254: v118.11,15.24 118.11,13.97 EDGE.CD1
  Bottom 0.254: v118.11,15.24 119.38,16.51 119.38,44.45 120.65,45.72 E25.4
IR00\  (via drill 0.61)
  Top 0.254: v54.61,80.01 40.64,80.01 39.37,78.74 E46.11
  Bottom 0.254: v54.61,80.01 54.61,63.5 46.99,55.88 46.99,15.24 48.26,13.97 EDGE.DD2
IR01\  (via drill 0.61)
  Top 0.254: v46.99,69.85 43.18,69.85 39.37,73.66 E46.9
  Bottom 0.254: v46.99,69.85 45.72,68.58 45.72,13.97 EDGE.DE2
JMP+JMS
  Top 0.254: E42.1 49.53,119.38 49.53,116.84 E42.2 52.07,116.84 57.15,111.76 E42.11
  Bottom 0.254: 46.99,101.6 46.99,114.3 49.53,116.84 E42.2 | 46.99,101.6 46.99,91.44 39.37,83.82 E46.13 | 46.99,101.6 40.64,107.95 40.64,176.53 39.37,177.8 E48.11
KEY_CTL\  (via drill 0.61)
  Top 0.254: v2.54,77.47 27.94,77.47 29.21,78.74 E46.4
  Bottom 0.254: v2.54,77.47 2.54,20.32 6.35,16.51 6.35,13.97 EDGE.DU2
LA  (via drill 0.61)
  Top 0.254: 163.83,50.8 163.83,48.26 E16.3 | 163.83,50.8 162.56,52.07 139.7,52.07 138.43,53.34 E25.14 | E16.2 163.83,50.8 | v73.66,143.51 66.04,143.51 64.77,142.24 E39.5 | v73.66,134.62 74.93,133.35 v167.64,133.35
  Bottom 0.254: v73.66,134.62 v73.66,143.51 | E19.4 163.83,144.78 163.83,142.24 E19.5 166.37,142.24 167.64,140.97 v167.64,133.35 167.64,52.07 166.37,50.8 E16.2
LOAD_ADDR  (via drill 0.61)
  Top 0.254: 59.69,31.75 58.42,30.48 v21.59,30.48 | 59.69,31.75 v60.96,33.02 | 59.69,31.75 v125.73,31.75
  Bottom 0.254: v60.96,33.02 60.96,44.45 59.69,45.72 E40.11 | v21.59,30.48 17.78,26.67 17.78,13.97 EDGE.DR2 | v125.73,31.75 125.73,38.1 128.27,40.64 E25.9
LOAD_CNTL  (via drill 0.61)
  Top 0.254: v200.66,19.05 199.39,17.78 185.42,17.78 184.15,16.51 v172.72,16.51
  Bottom 0.254: v200.66,19.05 200.66,44.45 199.39,45.72 E11.4 | v172.72,16.51 172.72,13.97 EDGE.BH2
MD00\  (via drill 0.61)
  Top 0.254: v146.05,130.81 v83.82,130.81 | v210.82,93.98 v144.78,93.98 | v219.71,36.83 v213.36,43.18 | v226.06,24.13 236.22,13.97 EDGE.AK1
  Bottom 0.254: v83.82,130.81 83.82,115.57 85.09,114.3 E37.12 | v146.05,130.81 146.05,105.41 144.78,104.14 v144.78,93.98 | v210.82,93.98 213.36,91.44 v213.36,43.18 | v219.71,36.83 226.06,30.48 v226.06,24.13
MD01\  (via drill 0.61)
  Top 0.254: v91.44,60.96 185.42,60.96 186.69,59.69 v218.44,59.69 | v218.44,27.94 232.41,13.97 EDGE.AL1 | v91.44,111.76 E37.11
  Bottom 0.254: v91.44,60.96 v91.44,111.76 | v218.44,59.69 v218.44,27.94
MD02\  (via drill 0.61)
  Top 0.254: v139.7,19.05 184.15,19.05 185.42,20.32 v215.9,20.32 | v223.52,20.32 229.87,13.97 EDGE.AM1
  Bottom 0.254: v139.7,19.05 133.35,25.4 133.35,43.18 130.81,45.72 E25.11 | v215.9,20.32 v223.52,20.32
MD03  (via drill 0.61)
  Top 0.254: v101.6,118.11 119.38,118.11 120.65,119.38 E27.1 | v81.28,57.15 135.89,57.15 137.16,55.88 201.93,55.88 204.47,53.34 E11.14 | v92.71,82.55 90.17,80.01 81.28,80.01 80.01,78.74 E36.4 | v92.71,111.76 E32.4
  Bottom 0.254: 101.6,138.43 v101.6,118.11 101.6,113.03 100.33,111.76 E32.4 | 101.6,138.43 100.33,139.7 E33.6 | 101.6,138.43 101.6,176.53 100.33,177.8 E34.4 | v81.28,57.15 81.28,77.47 80.01,78.74 E36.4 | v92.71,82.55 v92.71,111.76
MD03\  (via drill 0.61)
  Top 0.254: v214.63,25.4 222.25,17.78 222.25,13.97 EDGE.AP1
  Bottom 0.254: v214.63,25.4 214.63,35.56 207.01,43.18 E11.10
MD04\  (via drill 0.61)
  Top 0.254: 144.78,39.37 143.51,38.1 E20.7 | 144.78,39.37 v161.29,39.37 | v162.56,15.24 165.1,15.24 166.37,13.97 EDGE.BK1 | v110.49,40.64 118.11,40.64 119.38,39.37 144.78,39.37 | v111.76,106.68 E32.9
  Bottom 0.254: E32.9 105.41,106.68 104.14,107.95 104.14,140.97 105.41,142.24 E33.10 | v161.29,39.37 161.29,16.51 v162.56,15.24 | v111.76,106.68 111.76,80.01 110.49,78.74 v110.49,40.64
MD05\  (via drill 0.61)
  Top 0.254: v152.4,30.48 153.67,29.21 v160.02,29.21 | v160.02,15.24 161.29,15.24 162.56,13.97 EDGE.BL1
  Bottom 0.254: v152.4,30.48 152.4,46.99 151.13,48.26 E20.12 | v160.02,15.24 v160.02,29.21
MD06  (via drill 0.61)
  Top 0.254: v106.68,162.56 39.37,162.56 33.02,156.21 15.24,156.21 11.43,152.4 E53.1 | v154.94,121.92 v143.51,121.92 v113.03,121.92 | v157.48,172.72 E15.6
  Bottom 0.254: E34.11 105.41,177.8 104.14,176.53 104.14,165.1 v106.68,162.56 113.03,156.21 v113.03,121.92 | v143.51,121.92 143.51,119.38 E22.1 | 156.21,120.65 v154.94,121.92 | 156.21,120.65 156.21,106.68 154.94,105.41 154.94,57.15 151.13,53.34 E20.14 | v157.48,172.72 156.21,171.45 156.21,120.65
MD06\  (via drill 0.61)
  Top 0.254: v158.75,15.24 158.75,13.97 EDGE.BM1 | v156.21,40.64 E20.9
  Bottom 0.254: v156.21,40.64 158.75,38.1 v158.75,15.24
MD07  (via drill 0.61)
  Top 0.254: v12.7,170.18 12.7,182.88 13.97,182.88 15.24,184.15 91.44,184.15 96.52,179.07 102.87,179.07 104.14,180.34 E34.12 | v3.81,139.7 E53.6 | v132.08,50.8 138.43,50.8 140.97,48.26 E20.3 | v132.08,107.95 137.16,113.03 146.05,113.03 147.32,114.3 E22.14 | v154.94,171.45 203.2,171.45 204.47,170.18 E15.10 | v153.67,162.56 v113.03,162.56
  Bottom 0.254: v3.81,139.7 3.81,149.86 10.16,156.21 12.7,156.21 v12.7,170.18 | v132.08,107.95 v132.08,50.8 | v154.94,171.45 153.67,170.18 v153.67,162.56 153.67,119.38 152.4,118.11 152.4,115.57 151.13,114.3 E22.14 | v113.03,162.56 113.03,175.26 107.95,180.34 E34.12
MD07\  (via drill 0.61)
  Top 0.254: v156.21,41.91 144.78,41.91 143.51,43.18 E20.5 | v154.94,15.24 153.67,13.97 EDGE.BP1
  Bottom 0.254: v156.21,41.91 154.94,40.64 v154.94,15.24
MD08  (via drill 0.61)
  Top 0.254: v13.97,58.42 16.51,55.88 19.05,55.88 22.86,52.07 33.02,52.07 34.29,50.8 E45.13 | v13.97,137.16 E53.10 | v137.16,118.11 147.32,118.11 148.59,116.84 E22.15 | v135.89,171.45 133.35,173.99 111.76,173.99 109.22,171.45 104.14,171.45 104.14,175.26 E34.10 | v212.09,167.64 208.28,163.83 v135.89,163.83 12.7,163.83 v12.7,154.94
  Bottom 0.254: v13.97,58.42 v13.97,137.16 13.97,149.86 12.7,151.13 v12.7,154.94 | v137.16,118.11 135.89,119.38 v135.89,163.83 v135.89,171.45 | v212.09,167.64 212.09,182.88 E15.15
MD08\  (via drill 0.61)
  Top 0.254: v33.02,46.99 35.56,46.99 36.83,48.26 E45.12 | v31.75,15.24 31.75,13.97 EDGE.DK1
  Bottom 0.254: v33.02,46.99 33.02,29.21 31.75,27.94 v31.75,15.24
MD09\  (via drill 0.61)
  Top 0.254: v33.02,17.78 29.21,13.97 EDGE.DL1 | 41.91,41.91 40.64,40.64 E45.9 | 41.91,41.91 v43.18,43.18 | v73.66,110.49 101.6,110.49 102.87,109.22 E32.10 | v72.39,43.18 71.12,41.91 41.91,41.91
  Bottom 0.254: v33.02,17.78 33.02,26.67 34.29,27.94 34.29,38.1 36.83,40.64 E45.9 | v43.18,43.18 43.18,67.31 45.72,69.85 45.72,71.12 E41.7 | v73.66,110.49 72.39,109.22 v72.39,43.18
MD10\  (via drill 0.61)
  Top 0.254: v26.67,15.24 26.67,13.97 EDGE.DM1 | v48.26,74.93 55.88,74.93 57.15,76.2 E41.10 | v40.64,39.37 33.02,39.37 31.75,38.1 E45.7
  Bottom 0.254: v26.67,15.24 26.67,35.56 29.21,38.1 E45.7 | v48.26,74.93 41.91,68.58 41.91,44.45 40.64,43.18 v40.64,39.37
MD11\  (via drill 0.61)
  Top 0.254: E41.9 59.69,73.66 60.96,74.93 83.82,74.93 85.09,73.66 E36.9 | v22.86,16.51 20.32,13.97 EDGE.DP1 | v48.26,45.72 46.99,44.45 33.02,44.45 31.75,43.18 E45.5
  Bottom 0.254: v22.86,16.51 22.86,36.83 29.21,43.18 E45.5 | v48.26,45.72 48.26,52.07 60.96,52.07 60.96,72.39 59.69,73.66 E41.9
N$1  (via drill 0.61)
  Top 0.254: v93.98,97.79 128.27,97.79 129.54,96.52 143.51,96.52 144.78,95.25 v180.34,95.25 | v92.71,48.26 E35.12
  Bottom 0.254: v92.71,48.26 93.98,49.53 v93.98,97.79 | v180.34,95.25 180.34,147.32 177.8,149.86 177.8,165.1 151.13,191.77 144.78,191.77 144.78,181.61 143.51,180.34 E24.3
N$2  (via drill 0.61)
  Top 0.762: v118.11,86.36 E26.1
  Bottom 0.762: v118.11,86.36 116.84,87.63 116.84,115.57 114.3,118.11 J1.1
N$3
  Bottom 0.254: 132.08,176.53 132.08,110.49 130.81,109.22 E27.10 | 132.08,176.53 130.81,177.8 E29.11 | 132.08,176.53 132.08,181.61 130.81,182.88 E29.13
N$4  (via drill 0.61)
  Top 0.762: R4.1 134.62,85.09 101.6,85.09 100.33,86.36 E31.1 | v137.16,114.3 138.43,114.3 140.97,116.84 E22.2
  Bottom 0.762: v137.16,114.3 137.16,85.09 R4.1
N$5  (via drill 0.61)
  Top 0.762: v90.17,82.55 91.44,83.82 E31.2 | v91.44,114.3 E32.3
  Bottom 0.762: 97.79,76.2 97.79,73.66 E31.6 | 97.79,81.28 97.79,83.82 E31.2 | v91.44,114.3 90.17,113.03 v90.17,82.55 | 97.79,76.2 96.52,77.47 96.52,80.01 97.79,81.28 | 97.79,76.2 E31.5 | 97.79,81.28 E31.3
N$6
  Bottom 0.254: E36.3 80.01,81.28 81.28,82.55 81.28,83.82 82.55,85.09 82.55,106.68 80.01,109.22 E37.5
N$7  (via drill 0.61)
  Top 0.254: 96.52,44.45 60.96,44.45 59.69,43.18 E40.10 | 96.52,44.45 97.79,45.72 E30.4 | 119.38,44.45 120.65,43.18 E25.5 | 96.52,44.45 119.38,44.45 | 119.38,44.45 v133.35,44.45 152.4,44.45 154.94,46.99 195.58,46.99 196.85,48.26 E11.3 | v133.35,106.68 E27.9 | v125.73,115.57 v76.2,115.57 | v76.2,139.7 E39.9
  Bottom 0.254: v133.35,44.45 v133.35,106.68 | v76.2,115.57 v76.2,139.7 | v125.73,115.57 127,114.3 127,107.95 128.27,106.68 E27.9
N$8
  Bottom 0.254: E36.2 80.01,83.82 81.28,85.09 81.28,105.41 80.01,106.68 E37.6
N$9
  Bottom 0.254: E36.14 86.36,100.33 83.82,102.87 83.82,105.41 85.09,106.68 E37.9
N$10  (via drill 0.61)
  Top 0.254: v242.57,55.88 232.41,55.88 227.33,50.8 E6.2 | v242.57,105.41 246.38,109.22 E3.5
  Bottom 0.254: v242.57,55.88 v242.57,105.41 242.57,119.38 245.11,121.92 245.11,191.77 208.28,191.77 199.39,182.88 E15.2
N$11  (via drill 0.61)
  Top 0.254: v193.04,142.24 194.31,142.24 196.85,139.7 E14.6
  Bottom 0.254: v193.04,142.24 195.58,144.78 195.58,148.59 196.85,149.86 E14.2
N$12
  Bottom 0.254: E46.12 36.83,81.28 35.56,82.55 35.56,85.09 36.83,86.36 E46.14
N$13
  Bottom 0.254: E38.4 77.47,144.78 76.2,146.05 76.2,173.99 58.42,191.77 50.8,191.77 50.8,189.23 48.26,186.69 48.26,181.61 49.53,180.34 E44.3
N$14  (via drill 0.61)
  Top 0.254: v54.61,45.72 52.07,43.18 E40.5
  Bottom 0.254: v54.61,45.72 54.61,48.26 52.07,50.8 E40.2
N$15  (via drill 0.61)
  Top 0.254: v118.11,77.47 132.08,77.47 133.35,78.74 E21.4 | v115.57,73.66 114.3,72.39 v71.12,72.39
  Bottom 0.254: E40.4 49.53,45.72 48.26,44.45 48.26,31.75 53.34,26.67 71.12,26.67 v71.12,72.39 71.12,133.35 68.58,135.89 68.58,142.24 67.31,143.51 67.31,147.32 64.77,149.86 E39.2 | v118.11,77.47 115.57,74.93 v115.57,73.66
N$16  (via drill 0.61)
  Top 0.254: v134.62,52.07 109.22,52.07 107.95,50.8 E30.13 | v134.62,76.2 E21.5
  Bottom 0.254: v134.62,52.07 v134.62,76.2
N$17  (via drill 0.61)
  Top 0.254: v135.89,55.88 124.46,55.88 123.19,54.61 109.22,54.61 107.95,53.34 E30.14
  Bottom 0.254: v135.89,55.88 135.89,76.2 140.97,81.28 E21.3
N$18
  Bottom 0.254: 85.09,40.64 85.09,38.1 E35.8 | 85.09,40.64 83.82,41.91 83.82,44.45 85.09,45.72 E35.11 87.63,45.72 88.9,46.99 88.9,135.89 87.63,137.16 E38.8 85.09,137.16 80.01,142.24 E38.5 | 85.09,40.64 E35.9
N$19  (via drill 0.61)
  Top 0.254: v48.26,110.49 72.39,110.49 74.93,113.03 101.6,113.03 104.14,110.49 125.73,110.49 127,111.76 E27.11
  Bottom 0.254: v48.26,110.49 48.26,85.09 49.53,83.82 E41.2
N$20  (via drill 0.61)
  Top 0.254: v222.25,100.33 223.52,101.6 247.65,101.6 250.19,104.14 E3.7 | v219.71,171.45 214.63,171.45 212.09,173.99 200.66,173.99 199.39,175.26 E15.5
  Bottom 0.254: E6.5 224.79,43.18 222.25,45.72 v222.25,100.33 220.98,101.6 220.98,170.18 v219.71,171.45
N$21  (via drill 0.61)
  Top 0.254: v78.74,176.53 60.96,176.53 59.69,177.8 E44.11
  Bottom 0.254: 85.09,149.86 85.09,147.32 E38.12 | v78.74,176.53 83.82,171.45 83.82,151.13 85.09,149.86 | 85.09,149.86 E38.13
N$22  (via drill 0.61)
  Top 0.254: v95.25,143.51 96.52,144.78 E33.4 E33.11 | v95.25,170.18 97.79,172.72 E34.6 | E45.4 E45.11 46.99,45.72 48.26,46.99 v102.87,46.99 124.46,46.99 | 124.46,46.99 123.19,48.26 E25.3 | 124.46,46.99 138.43,46.99 139.7,45.72 E20.4 E20.11
  Bottom 0.254: E33.11 105.41,144.78 105.41,147.32 E33.12 | v95.25,170.18 v95.25,143.51 95.25,109.22 97.79,106.68 E32.6 100.33,106.68 102.87,104.14 v102.87,46.99 | E20.10 148.59,43.18 148.59,45.72 E20.11 | E20.6 140.97,40.64 139.7,41.91 139.7,44.45 140.97,45.72 E20.4
N$23
  Top 0.254: E38.6 E38.9
  Bottom 0.254: E38.10 85.09,142.24 85.09,139.7 E38.9
N$24
  Bottom 0.254: E23.13 151.13,149.86 152.4,151.13 152.4,168.91 151.13,170.18 E24.8
N$25
  Top 0.254: E43.6 49.53,139.7 52.07,142.24 E43.10
  Bottom 0.254: E43.13 54.61,149.86 53.34,148.59 53.34,143.51 54.61,142.24 E43.10
N$26  (via drill 0.61)
  Top 0.254: E36.5 E36.10 87.63,76.2 88.9,74.93 124.46,74.93 v125.73,73.66
  Bottom 0.254: E36.6 77.47,73.66 77.47,76.2 E36.5 | v125.73,73.66 125.73,53.34 128.27,50.8 E25.13
N$27
  Top 0.254: E34.3 100.33,180.34 104.14,184.15 118.11,184.15 119.38,185.42 E29.1
  Bottom 0.254: E31.8 105.41,71.12 105.41,73.66 E31.9 107.95,73.66 109.22,74.93 109.22,104.14 110.49,105.41 110.49,157.48 102.87,165.1 102.87,177.8 100.33,180.34 E34.3 | E29.10 128.27,175.26 125.73,177.8 125.73,184.15 124.46,185.42 E29.1
N$28  (via drill 0.61)
  Top 0.254: v201.93,149.86 199.39,152.4 E14.1
  Bottom 0.254: v201.93,149.86 201.93,139.7 204.47,137.16 E14.8
N$29  (via drill 0.61)
  Top 0.254: v43.18,73.66 44.45,72.39 69.85,72.39 71.12,71.12 E36.7
  Bottom 0.254: v43.18,73.66 43.18,74.93 49.53,81.28 E41.3
N$30  (via drill 0.61)
  Top 0.254: v62.23,127 71.12,135.89 101.6,135.89 105.41,139.7 E33.9 | v62.23,81.28 60.96,80.01 55.88,80.01 54.61,78.74 E41.4
  Bottom 0.254: E45.14 39.37,53.34 40.64,54.61 40.64,69.85 49.53,78.74 E41.4 | v62.23,81.28 v62.23,127
N$31  (via drill 0.61)
  Top 0.254: 113.03,113.03 118.11,113.03 119.38,114.3 E27.3 | 113.03,113.03 109.22,113.03 107.95,111.76 E32.11 | v27.94,72.39 33.02,72.39 35.56,74.93 46.99,74.93 48.26,76.2 E41.5 | v113.03,111.76 113.03,113.03 | v27.94,62.23 v113.03,62.23
  Bottom 0.254: v27.94,72.39 v27.94,62.23 27.94,52.07 29.21,50.8 E45.2 | E41.6 49.53,73.66 49.53,76.2 E41.5 | v113.03,62.23 v113.03,111.76
N$32  (via drill 0.61)
  Top 0.254: v134.62,148.59 144.78,148.59 146.05,147.32 E23.12 | v135.89,104.14 137.16,102.87 v158.75,102.87
  Bottom 0.254: v134.62,148.59 134.62,116.84 135.89,115.57 v135.89,104.14 | v158.75,102.87 162.56,99.06 162.56,82.55 163.83,81.28 E17.3
N$33  (via drill 0.61)
  Top 0.254: v147.32,58.42 148.59,59.69 v168.91,59.69 | v158.75,173.99 147.32,173.99 144.78,176.53 111.76,176.53 107.95,172.72 E34.9
  Bottom 0.254: v147.32,58.42 147.32,50.8 E20.2 | v168.91,59.69 168.91,152.4 158.75,162.56 v158.75,173.99
N$34  (via drill 0.61)
  Top 0.254: v156.21,105.41 114.3,105.41 111.76,107.95 101.6,107.95 100.33,109.22 E32.5
  Bottom 0.254: 96.52,140.97 96.52,110.49 97.79,109.22 E32.5 | 96.52,140.97 97.79,142.24 E33.5 | 96.52,140.97 96.52,173.99 97.79,175.26 E34.5 | v156.21,105.41 156.21,55.88 151.13,50.8 E20.13
N$35  (via drill 0.61)
  Top 0.254: v95.25,87.63 93.98,87.63 87.63,81.28 E36.12 | v93.98,177.8 92.71,179.07 45.72,179.07 44.45,180.34 E48.12
  Bottom 0.254: R7.1 43.18,180.34 E48.12 | v95.25,87.63 95.25,107.95 93.98,109.22 v93.98,177.8
N$36  (via drill 0.61)
  Top 0.254: v187.96,143.51 203.2,143.51 204.47,142.24 E14.10 | v151.13,193.04 v36.83,193.04
  Bottom 0.254: v187.96,143.51 185.42,146.05 185.42,158.75 v151.13,193.04 | v36.83,193.04 35.56,191.77 35.56,176.53 36.83,175.26 E48.10
N$37  (via drill 0.61)
  Top 0.254: v161.29,139.7 E23.9
  Bottom 0.254: v161.29,139.7 161.29,116.84 163.83,114.3 E18.3
N$38
  Top 0.254: E21.8 148.59,71.12 147.32,72.39 124.46,72.39 123.19,73.66 E26.6
  Bottom 0.254: E26.6 120.65,73.66 120.65,76.2 E26.5
N$39  (via drill 0.61)
  Top 0.254: v161.29,91.44 v130.81,91.44
  Bottom 0.254: v161.29,91.44 161.29,45.72 163.83,43.18 E16.5 | v130.81,91.44 130.81,104.14 E27.8
N$40  (via drill 0.61)
  Top 0.254: E12.10 204.47,76.2 204.47,78.74 E12.11 | v124.46,102.87 60.96,102.87 59.69,104.14 E42.8 | v129.54,97.79 143.51,97.79 144.78,96.52 v200.66,96.52
  Bottom 0.254: 204.47,83.82 203.2,82.55 203.2,80.01 204.47,78.74 E12.11 | v129.54,97.79 v124.46,102.87 | v200.66,96.52 201.93,95.25 201.93,86.36 204.47,83.82 | 204.47,83.82 E12.13
N$41
  Bottom 0.254: E39.10 69.85,142.24 68.58,143.51 68.58,148.59 69.85,149.86 E39.13
N$42  (via drill 0.61)
  Top 0.254: R2.1 158.75,74.93 168.91,74.93 170.18,76.2 E17.10 v193.04,76.2
  Bottom 0.254: v193.04,76.2 193.04,107.95 196.85,111.76 E13.4
N$43  (via drill 0.61)
  Top 0.254: v95.25,78.74 96.52,80.01 167.64,80.01 170.18,82.55 v190.5,82.55
  Bottom 0.254: v95.25,78.74 95.25,50.8 97.79,48.26 E30.3 | v190.5,82.55 191.77,83.82 191.77,139.7 196.85,144.78 E14.4
N$44  (via drill 0.61)
  Top 0.254: v68.58,111.76 62.23,111.76 59.69,114.3 E42.12 | v69.85,101.6 74.93,96.52 127,96.52 128.27,95.25 139.7,95.25 142.24,92.71 v195.58,92.71
  Bottom 0.254: E12.9 204.47,73.66 200.66,77.47 200.66,85.09 199.39,86.36 E12.1 196.85,86.36 196.85,91.44 v195.58,92.71 | v68.58,111.76 69.85,110.49 v69.85,101.6
N$45  (via drill 0.61)
  Top 0.254: E3.9 257.81,101.6 256.54,100.33 246.38,100.33 v240.03,93.98 227.33,93.98 v218.44,102.87 | v218.44,170.18 209.55,170.18 207.01,172.72 E15.11
  Bottom 0.254: v240.03,93.98 240.03,74.93 237.49,72.39 237.49,43.18 234.95,40.64 E6.11 | v218.44,102.87 v218.44,170.18
N$47  (via drill 0.61)
  Top 0.254: v160.02,149.86 158.75,151.13 144.78,151.13 143.51,152.4 E23.1
  Bottom 0.254: v160.02,149.86 160.02,110.49 163.83,106.68 E18.6
N$48  (via drill 0.61)
  Top 0.254: v109.22,105.41 63.5,105.41 59.69,109.22 E42.10 | v109.22,116.84 E27.2
  Bottom 0.254: v109.22,105.41 v109.22,116.84
N$49  (via drill 0.61)
  Top 0.254: v186.69,80.01 175.26,80.01 173.99,81.28 E17.12 | v190.5,147.32 E14.3
  Bottom 0.254: v186.69,80.01 190.5,83.82 v190.5,147.32
N$50  (via drill 0.61)
  Top 0.254: v60.96,146.05 73.66,146.05 76.2,143.51 93.98,143.51 95.25,142.24 96.52,143.51 119.38,143.51 120.65,144.78 E28.4
  Bottom 0.254: v60.96,146.05 60.96,87.63 59.69,86.36 E41.14 | E28.2 120.65,149.86 119.38,148.59 119.38,146.05 120.65,144.78 E28.4
N$51
  Top 0.254: E13.6 196.85,106.68 195.58,105.41 170.18,105.41 170.18,109.22 E18.10
  Bottom 0.254: E18.10 173.99,109.22 175.26,110.49 175.26,115.57 173.99,116.84 E18.13
N$52  (via drill 0.61)
  Top 0.254: v119.38,167.64 120.65,166.37 v143.51,166.37 | v146.05,138.43 161.29,138.43 162.56,139.7 E19.6
  Bottom 0.254: v119.38,167.64 119.38,179.07 120.65,180.34 E29.3 | v143.51,166.37 146.05,163.83 v146.05,138.43
N$53  (via drill 0.61)
  Top 0.254: v151.13,189.23 137.16,189.23 134.62,191.77 v113.03,191.77
  Bottom 0.254: E43.2 46.99,149.86 45.72,151.13 45.72,187.96 50.8,193.04 113.03,193.04 v113.03,191.77 113.03,189.23 118.11,184.15 124.46,184.15 124.46,179.07 123.19,177.8 E29.4 | v151.13,189.23 175.26,165.1 175.26,138.43 173.99,137.16 E19.8
N$54  (via drill 0.61)
  Top 0.254: E33.3 100.33,147.32 101.6,146.05 v111.76,146.05 114.3,146.05 116.84,148.59 127,148.59 128.27,149.86 E28.13 | v114.3,81.28 E31.12
  Bottom 0.254: E31.11 105.41,78.74 105.41,81.28 E31.12 | E28.10 128.27,142.24 127,143.51 127,148.59 128.27,149.86 E28.13 | v114.3,81.28 114.3,116.84 111.76,119.38 v111.76,146.05
N$55
  Top 0.254: E28.3 E28.12
N$56
  Top 0.254: E28.6 E28.9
